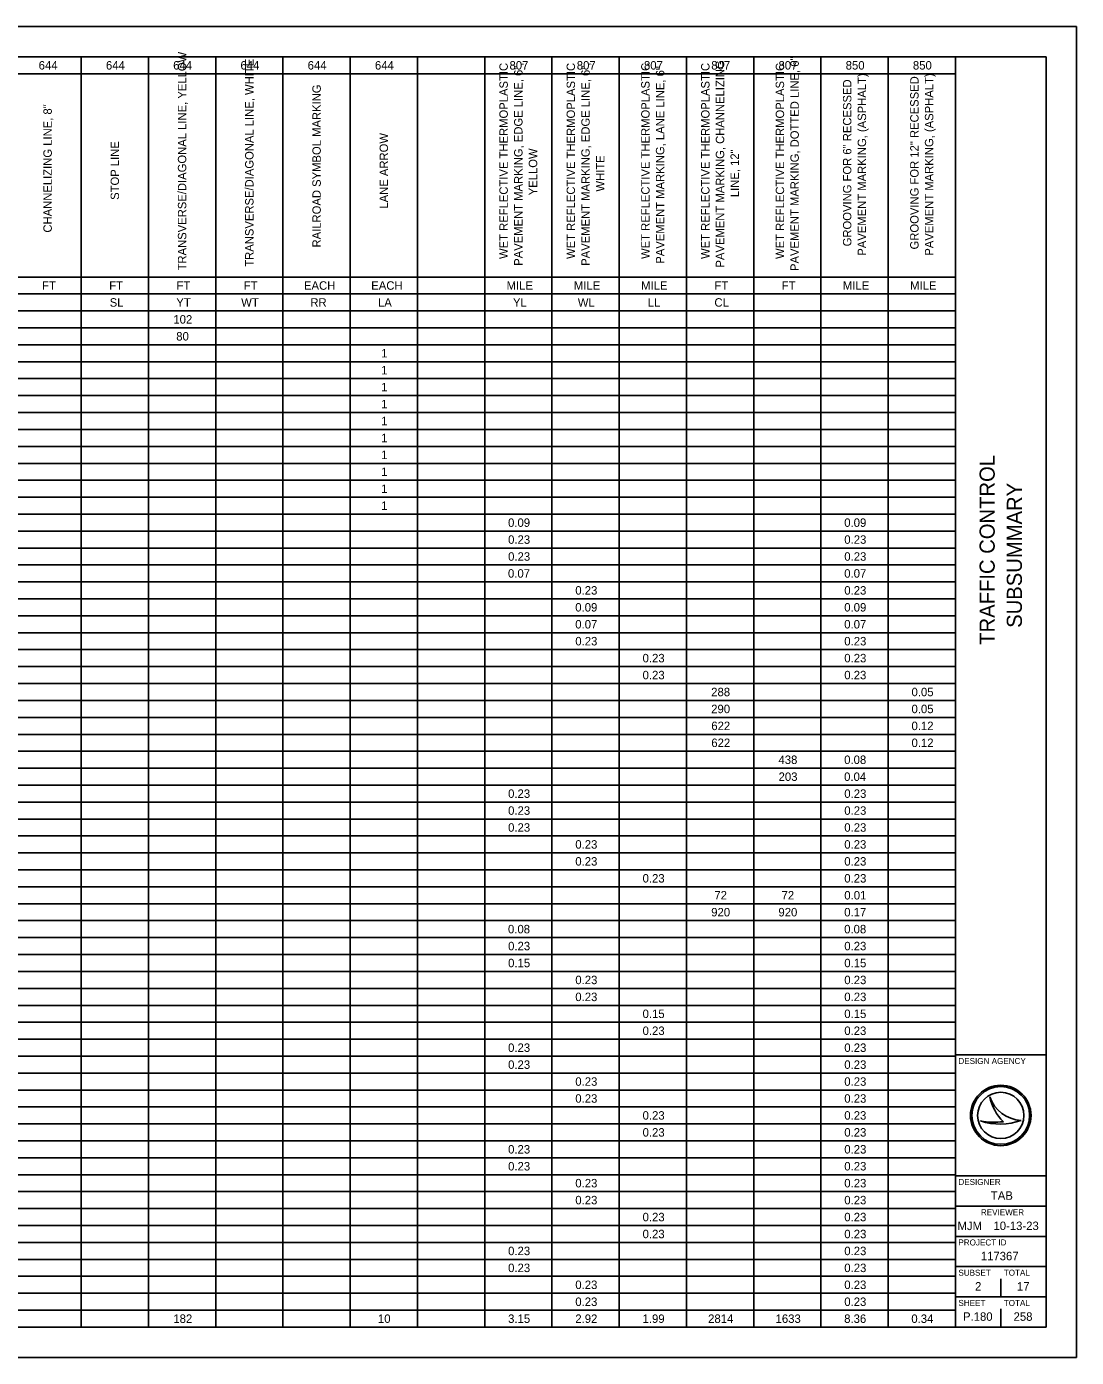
# Model space of a CAD drawing. Extents: x 0 to 34, y 0 to 22.
# Drawn here: x 16.65 to 34, y 0 to 22 of the extents above; entities that cross this region are included whole.
import ezdxf

# ---------------------------------------------------------------- set-up
doc = ezdxf.new("R2010")
doc.units = 0
for name, color, linetype in [('SH_Border', 7, 'Continuous'), ('SH_Cut_Line', 7, 'Continuous'), ('SH_Data', 7, 'Continuous'), ('SH_Text', 7, 'Continuous')]:
    doc.layers.add(name, color=color, linetype=linetype)

msp = doc.modelspace()

# ---------------------------------------------------------------- linework, layer by layer
at = {"layer": 'SH_Border'}
for p, q in [((32, 0.5), (32, 21.5)), ((32, 5), (33.5, 5)), ((32, 3), (33.5, 3)), ((32, 2.5), (33.5, 2.5)), ((32, 2), (33.5, 2)), ((32, 1.5), (33.5, 1.5)), ((32, 1), (33.5, 1))]:
    msp.add_line(p, q, dxfattribs=at)
msp.add_lwpolyline([(1.5, 21.5), (33.5, 21.5), (33.5, 0.5), (1.5, 0.5)], close=True, dxfattribs=at)
at = {"layer": 'SH_Cut_Line'}
msp.add_lwpolyline([(0, 0), (34, 0), (34, 22), (0, 22)], close=True, dxfattribs=at)
at = {"layer": 'SH_Data'}
for p, q in [((32.567, 4.31), (32.567, 4.31)), ((32.75, 4), (32.75, 4)), ((32.417, 3.91), (32.417, 3.91)), ((33.087, 3.919), (33.087, 3.919)), ((32.75, 1), (32.75, 1.3)), ((32.375, 0.675), (32.375, 0.675)), ((32.75, 0.5), (32.75, 0.8))]:
    msp.add_line(p, q, dxfattribs=at)
for radius in [0.5, 0.477, 0.477, 0.382]:
    msp.add_circle((32.75, 4), radius, dxfattribs=at)
for centre, radius, start, end in [((33.116, 4.498), 0.58, 198.9257, 198.9319), ((33.347, 4.47), 0.796, 191.6379, 191.6421), ((33.116, 4.498), 0.58, 198.9319, 267.1657), ((33.347, 4.47), 0.796, 191.6421, 226.0947), ((32.739, 4.87), 1.013, 251.4576, 290.0832), ((32.648, 5.154), 1.266, 259.4964, 259.4995), ((32.739, 4.87), 1.013, 251.4527, 251.4576), ((32.648, 5.154), 1.266, 259.4995, 276.6672)]:
    msp.add_arc(centre, radius, start, end, dxfattribs=at)
at = {"layer": 'SH_Text'}
for p, q in [((1.5, 21.5), (32, 21.5)), ((17.551, 21.5), (17.551, 0.5)), ((18.662, 21.5), (18.662, 0.5)), ((19.774, 21.5), (19.774, 0.5)), ((20.885, 21.5), (20.885, 0.5)), ((21.997, 21.5), (21.997, 0.5)), ((23.108, 21.5), (23.108, 0.5)), ((24.22, 21.5), (24.22, 0.5)), ((25.331, 21.5), (25.331, 0.5)), ((26.443, 21.5), (26.443, 0.5)), ((27.554, 21.5), (27.554, 0.5)), ((28.666, 21.5), (28.666, 0.5)), ((29.777, 21.5), (29.777, 0.5)), ((30.889, 21.5), (30.889, 0.5)), ((32, 21.5), (32, 0.5)), ((8.659, 21.22), (32, 21.22)), ((8.659, 17.86), (32, 17.86)), ((1.5, 17.58), (32, 17.58)), ((1.5, 17.3), (32, 17.3)), ((1.5, 17.02), (32, 17.02)), ((1.5, 16.74), (32, 16.74)), ((1.5, 16.46), (32, 16.46)), ((1.5, 16.18), (32, 16.18)), ((1.5, 15.9), (32, 15.9)), ((1.5, 15.62), (32, 15.62)), ((1.5, 15.34), (32, 15.34)), ((1.5, 15.06), (32, 15.06)), ((1.5, 14.78), (32, 14.78)), ((1.5, 14.5), (32, 14.5)), ((1.5, 14.22), (32, 14.22)), ((1.5, 13.94), (32, 13.94)), ((1.5, 13.66), (32, 13.66)), ((1.5, 13.38), (32, 13.38)), ((1.5, 13.1), (32, 13.1)), ((1.5, 12.82), (32, 12.82)), ((1.5, 12.54), (32, 12.54)), ((1.5, 12.26), (32, 12.26)), ((1.5, 11.98), (32, 11.98)), ((1.5, 11.7), (32, 11.7)), ((1.5, 11.42), (32, 11.42)), ((1.5, 11.14), (32, 11.14)), ((1.5, 10.86), (32, 10.86)), ((1.5, 10.58), (32, 10.58)), ((1.5, 10.3), (32, 10.3)), ((1.5, 10.02), (32, 10.02)), ((1.5, 9.74), (32, 9.74)), ((1.5, 9.46), (32, 9.46)), ((1.5, 9.18), (32, 9.18)), ((1.5, 8.9), (32, 8.9)), ((1.5, 8.62), (32, 8.62)), ((1.5, 8.34), (32, 8.34)), ((1.5, 8.06), (32, 8.06)), ((1.5, 7.78), (32, 7.78)), ((1.5, 7.5), (32, 7.5)), ((1.5, 7.22), (32, 7.22)), ((1.5, 6.94), (32, 6.94)), ((1.5, 6.66), (32, 6.66)), ((1.5, 6.38), (32, 6.38)), ((1.5, 6.1), (32, 6.1)), ((1.5, 5.82), (32, 5.82)), ((1.5, 5.54), (32, 5.54)), ((1.5, 5.26), (32, 5.26)), ((1.5, 4.98), (32, 4.98)), ((1.5, 4.7), (32, 4.7)), ((1.5, 4.42), (32, 4.42)), ((1.5, 4.14), (32, 4.14)), ((1.5, 3.86), (32, 3.86)), ((1.5, 3.58), (32, 3.58)), ((1.5, 3.3), (32, 3.3)), ((1.5, 3.02), (32, 3.02)), ((1.5, 2.74), (32, 2.74)), ((1.5, 2.46), (32, 2.46)), ((1.5, 2.18), (32, 2.18)), ((1.5, 1.9), (32, 1.9)), ((1.5, 1.62), (32, 1.62)), ((1.5, 1.34), (32, 1.34)), ((1.5, 1.06), (32, 1.06)), ((1.5, 0.78), (32, 0.78)), ((1.5, 0.5), (32, 0.5))]:
    msp.add_line(p, q, dxfattribs=at)

# ---------------------------------------------------------------- texts
at = {"layer": 'SH_Data'}
for s, p in [('TRAFFIC CONTROL', (32.65, 11.78)), ('SUBSUMMARY', (33.1, 12.061))]:
    msp.add_text(s, height=0.25, rotation=90, dxfattribs=at).set_placement(p)
for s, height, p in [('DESIGN AGENCY', 0.1, (32.05, 4.85)), ('DESIGNER', 0.1, (32.05, 2.85)), ('TAB', 0.14, (32.586, 2.605)), ('REVIEWER', 0.1, (32.422, 2.35)), ('MJM', 0.14, (32.035, 2.105)), ('10-13-23', 0.14, (32.629, 2.105)), ('PROJECT ID', 0.1, (32.05, 1.85)), ('117367', 0.14, (32.42, 1.605)), ('SUBSET', 0.1, (32.05, 1.35)), ('TOTAL', 0.1, (32.8, 1.35)), ('2', 0.14, (32.325, 1.105)), ('17', 0.14, (33.018, 1.105)), ('SHEET', 0.1, (32.05, 0.85)), ('TOTAL', 0.1, (32.8, 0.85)), ('P.180', 0.14, (32.126, 0.605)), ('258', 0.14, (32.962, 0.605))]:
    msp.add_text(s, height=height, dxfattribs=at).set_placement(p)
at = {"layer": 'SH_Text'}
for s, height, p in [('TRANSVERSE/DIAGONAL LINE, YELLOW', 0.13893, (19.288, 17.97)), ('TRANSVERSE/DIAGONAL LINE, WHITE', 0.13893, (20.399, 18.031)), ('WET REFLECTIVE THERMOPLASTIC ', 0.13893, (24.602, 18.159)), ('PAVEMENT MARKING, EDGE LINE, 6", ', 0.13893, (24.845, 18.046)), ('WET REFLECTIVE THERMOPLASTIC ', 0.13893, (25.713, 18.159)), ('PAVEMENT MARKING, EDGE LINE, 6", ', 0.13893, (25.956, 18.046)), ('WET REFLECTIVE THERMOPLASTIC ', 0.13893, (26.946, 18.159)), ('WET REFLECTIVE THERMOPLASTIC ', 0.13893, (27.936, 18.159)), ('PAVEMENT MARKING, CHANNELIZING ', 0.13893, (28.179, 18.017)), ('WET REFLECTIVE THERMOPLASTIC ', 0.13893, (29.169, 18.159)), ('PAVEMENT MARKING, DOTTED LINE, 6"', 0.13893, (29.412, 17.96)), ('PAVEMENT MARKING, LANE LINE, 6"', 0.13893, (27.189, 18.08)), ('PAVEMENT MARKING, (ASPHALT)', 0.13893, (30.524, 18.213)), ('GROOVING FOR 12" RECESSED ', 0.13893, (31.392, 18.316)), ('PAVEMENT MARKING, (ASPHALT)', 0.13893, (31.635, 18.213)), ('RAILROAD SYMBOL MARKING', 0.13893, (21.511, 18.349)), ('GROOVING FOR 6" RECESSED ', 0.13893, (30.281, 18.367)), ('CHANNELIZING LINE, 8"', 0.13893, (17.065, 18.595)), ('LANE ARROW', 0.1389, (22.622, 18.992)), ('STOP LINE', 0.1389, (18.176, 19.136)), ('YELLOW', 0.1389, (25.088, 19.212)), ('WHITE', 0.1389, (26.2, 19.273)), ('LINE, 12"', 0.1389, (28.422, 19.181))]:
    msp.add_text(s, height=height, rotation=90, dxfattribs=at).set_placement(p)
for s, p in [('644', (16.848, 21.29)), ('644', (17.96, 21.29)), ('644', (19.071, 21.29)), ('644', (20.183, 21.29)), ('644', (21.294, 21.29)), ('644', (22.406, 21.29)), ('807', (24.63, 21.29)), ('807', (25.742, 21.29)), ('807', (26.853, 21.29)), ('807', (27.965, 21.29)), ('807', (29.076, 21.29)), ('850', (30.187, 21.29)), ('850', (31.298, 21.29)), ('FT', (16.903, 17.65)), ('FT', (18.014, 17.65)), ('FT', (19.126, 17.65)), ('FT', (20.237, 17.65)), ('EACH', (21.232, 17.65)), ('EACH', (22.344, 17.65)), ('MILE', (24.582, 17.65)), ('MILE', (25.694, 17.65)), ('MILE', (26.805, 17.65)), ('FT', (28.017, 17.65)), ('FT', (29.129, 17.65)), ('MILE', (30.139, 17.65)), ('MILE', (31.251, 17.65)), ('SL', (18.021, 17.37)), ('YT', (19.123, 17.37)), ('WT', (20.195, 17.37)), ('RR', (21.338, 17.37)), ('LA', (22.456, 17.37)), ('YL', (24.687, 17.37)), ('WL', (25.759, 17.37)), ('LL', (26.916, 17.37)), ('CL', (28.017, 17.37)), ('102', (19.074, 17.09)), ('80', (19.122, 16.81)), ('1', (22.508, 16.53)), ('1', (22.508, 16.25)), ('1', (22.508, 15.97)), ('1', (22.508, 15.69)), ('1', (22.508, 15.41)), ('1', (22.508, 15.13)), ('1', (22.508, 14.85)), ('1', (22.508, 14.57)), ('1', (22.508, 14.29)), ('1', (22.508, 14.01)), ('0.09', (24.606, 13.73)), ('0.09', (30.163, 13.73)), ('0.23', (24.607, 13.45)), ('0.23', (30.164, 13.45)), ('0.23', (24.607, 13.17)), ('0.23', (30.164, 13.17)), ('0.07', (24.605, 12.89)), ('0.07', (30.163, 12.89)), ('0.23', (25.718, 12.61)), ('0.23', (30.164, 12.61)), ('0.09', (25.717, 12.33)), ('0.09', (30.163, 12.33)), ('0.07', (25.717, 12.05)), ('0.07', (30.163, 12.05)), ('0.23', (25.718, 11.77)), ('0.23', (30.164, 11.77)), ('0.23', (26.83, 11.49)), ('0.23', (30.164, 11.49)), ('0.23', (26.83, 11.21)), ('0.23', (30.164, 11.21)), ('288', (27.964, 10.93)), ('0.05', (31.275, 10.93)), ('290', (27.964, 10.65)), ('0.05', (31.275, 10.65)), ('622', (27.966, 10.37)), ('0.12', (31.275, 10.37)), ('622', (27.966, 10.09)), ('0.12', (31.275, 10.09)), ('438', (29.076, 9.81)), ('0.08', (30.162, 9.81)), ('203', (29.078, 9.53)), ('0.04', (30.161, 9.53)), ('0.23', (24.607, 9.25)), ('0.23', (30.164, 9.25)), ('0.23', (24.607, 8.97)), ('0.23', (30.164, 8.97)), ('0.23', (24.607, 8.69)), ('0.23', (30.164, 8.69)), ('0.23', (25.718, 8.41)), ('0.23', (30.164, 8.41)), ('0.23', (25.718, 8.13)), ('0.23', (30.164, 8.13)), ('0.23', (26.83, 7.85)), ('0.23', (30.164, 7.85)), ('72', (28.016, 7.57)), ('72', (29.127, 7.57)), ('0.01', (30.164, 7.57)), ('920', (27.964, 7.29)), ('920', (29.075, 7.29)), ('0.17', (30.163, 7.29)), ('0.08', (24.605, 7.01)), ('0.08', (30.162, 7.01)), ('0.23', (24.607, 6.73)), ('0.23', (30.164, 6.73)), ('0.15', (24.607, 6.45)), ('0.15', (30.164, 6.45)), ('0.23', (25.718, 6.17)), ('0.23', (30.164, 6.17)), ('0.23', (25.718, 5.89)), ('0.23', (30.164, 5.89)), ('0.15', (26.83, 5.61)), ('0.15', (30.164, 5.61)), ('0.23', (26.83, 5.33)), ('0.23', (30.164, 5.33)), ('0.23', (24.607, 5.05)), ('0.23', (30.164, 5.05)), ('0.23', (24.607, 4.77)), ('0.23', (30.164, 4.77)), ('0.23', (25.718, 4.49)), ('0.23', (30.164, 4.49)), ('0.23', (25.718, 4.21)), ('0.23', (30.164, 4.21)), ('0.23', (26.83, 3.93)), ('0.23', (30.164, 3.93)), ('0.23', (26.83, 3.65)), ('0.23', (30.164, 3.65)), ('0.23', (24.607, 3.37)), ('0.23', (30.164, 3.37)), ('0.23', (24.607, 3.09)), ('0.23', (30.164, 3.09)), ('0.23', (25.718, 2.81)), ('0.23', (30.164, 2.81)), ('0.23', (25.718, 2.53)), ('0.23', (30.164, 2.53)), ('0.23', (26.83, 2.25)), ('0.23', (30.164, 2.25)), ('0.23', (26.83, 1.97)), ('0.23', (30.164, 1.97)), ('0.23', (24.607, 1.69)), ('0.23', (30.164, 1.69)), ('0.23', (24.607, 1.41)), ('0.23', (30.164, 1.41)), ('0.23', (25.718, 1.13)), ('0.23', (30.164, 1.13)), ('0.23', (25.718, 0.85)), ('0.23', (30.164, 0.85)), ('182', (19.074, 0.57)), ('10', (22.456, 0.57)), ('3.15', (24.607, 0.57)), ('2.92', (25.718, 0.57)), ('1.99', (26.829, 0.57)), ('2814', (27.913, 0.57)), ('1633', (29.028, 0.57)), ('8.36', (30.162, 0.57)), ('0.34', (31.272, 0.57))]:
    msp.add_text(s, height=0.14, dxfattribs=at).set_placement(p)

doc.saveas('drawing.dxf')
